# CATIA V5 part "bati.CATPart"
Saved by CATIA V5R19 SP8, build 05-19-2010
Part number: bati
Bounding box of the stored display mesh (mm): x 43.851 to 95, y -33.659 to 317.961, z 22.484 to 100.684
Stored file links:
  G:\EU_thinkMotion\CFAO_2010\MMS_groupe3\MMS_groupe3\A reprendre\amenand\amenand\bati.CATPart
  F:\thinkmotion CFAO v12.1\essuie_glace.CATProduct
  G:\EU_thinkMotion\CFAO_2010\MMS_groupe3\MMS_groupe3\A reprendre\amenand\amenand\squelette_bielle_manivelle.CATPart
  G:\EU_thinkMotion\CFAO_2010\MMS_groupe3\MMS_groupe3\A reprendre\amenand\amenand\bielle_manivelle.CATPart
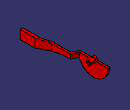
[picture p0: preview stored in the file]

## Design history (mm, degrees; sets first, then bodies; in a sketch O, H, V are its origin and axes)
Set1
  Plane1: linked copy from another document
  Point1: linked copy from another document
  Point2: linked copy from another document
  Plane2 to Plane4: linked copy from another document
Body1 (main body)
  Sketch1 on Plane1, origin (95, 0, 0), H (0, 1, 0), V (0, 0, 1)
    line L1 (317.9612, 88.9602) -> (264.4635, 88.4688)
    point P1 (317.9612, 88.9602)
    point P2 (-34.0239, 85.7271)
    reference projected point E1 (251.964, 88.354) from Point1
    line L2 (-34.0239, 85.7271) -> (-33.6588, 45.9731)
    line L3 (-33.6588, 45.9731) -> (33.3384, 46.5885)
    reference projected point E2 (0.0847, 66.2839) from Point2
    reference projected point E3 (0.0847, 66.2839) from Point2
    line L4 (33.3384, 46.5885) -> (146.176, 67.6258)
    line L5 (146.176, 67.6258) -> (189.1742, 68.0207)
    arc A1 centre (251.964, 88.354) radius 66 from (189.1742, 68.0207) to (317.9612, 88.9602) ccw
    point P7 (251.964, 88.354)
    reference projected point E4 (251.964, 88.354) from Point1
    point P8 (239.4645, 88.2392)
    line L6 (239.4645, 88.2392) -> (-34.0239, 85.7271)
    arc A2 centre (251.964, 88.354) radius 12.5 from (264.4635, 88.4688) to (239.4645, 88.2392) ccw
    point P9 (251.964, 88.354)
    reference projected point E5 (251.964, 88.354) from Point1
    point P11 (239.4645, 88.2392)
    length L3 = 67
    distance L3 E2 = 20
    distance L1 E3 = 20
    radius A1 = 66
    length L5 = 43
    distance P1 P2 = 352
    distance L3 L5 = 20
    radius A2 = 12.5
    coincidence: L1 E1, P7 E4, L1 L6, P9 E5, P8 P11
    fix: L1
    perpendicularity: L1 L2
    parallelism: L3 L1, L5 L1
  Sketch2 on xy-plane, origin (0, 0, 0), H (1, 0, 0), V (0, 1, 0)
    line L1 (83, -33.6588) -> (95, -33.6588)
    point P2 (95, -33.6588)
    reference projected point E1 (95, -33.6588) from vertex [element of Sketch1 | element of Sketch1]
    line L2 (83, -33.6588) -> (83, 46.0526)
    line L3 (95, -33.6588) -> (95, 33.5512)
    line L4 (95, 33.5512) -> (79.896, 92.151)
    point P5 (79.896, 92.151)
    line L5 (79.896, 92.151) -> (79.896, 177.3502)
    line L6 (83, 46.0526) -> (71.396, 91.0732)
    line L7 (71.396, 91.0732) -> (71.396, 171.742)
    line L8 (79.896, 177.3502) -> (52.3512, 189.1371)
    line L9 (52.3512, 189.1371) -> (52.3512, 321.1371)
    line L10 (43.8512, 183.5288) -> (43.8512, 321.1371)
    line L11 (43.8512, 321.1371) -> (52.3512, 321.1371)
    line L12 (71.396, 171.742) -> (43.8512, 183.5288)
    reference intersected line E2 through (83, 0) direction (0, 1) from Plane3
    distance L5 L7 = 8.5
    length L9 = 132
    distance L9 L10 = 8.5
    distance L8 L12 = 8.5
    distance L4 L6 = 8.5
    coincidence: P2 E1, L2 E2
    vertical: L5 V, L7 V, L9 V, L10 V, L3 V
    horizontal: L11 H, L1 H
    fix: P5, L4, L5, L8, L9
  SolidCombine1: FirstComponentProfile Sketch1, FirstComponentDirection Sketch1, SecondComponentProfile Sketch2, SecondComponentDirection Sketch2
  Sketch3 on face of SolidCombine1 from Sketch2.L10, origin (43.8512, 188.6989, 0), H (0, 1, 0), V (0, 0, 1)
    circle A1 centre (63.2651, 88.354) radius 11
    point P1 (63.2651, 88.354)
    reference projected point E1 (63.2651, 88.354) from Point1
    radius A1 = 11
    coincidence: P1 E1
  Pad1: profile Sketch3, direction (1, 0, 0), up to Plane2
  Sketch4 on face of SolidCombine1 from Sketch2.L10, origin (43.8512, 250.7075, 68.7488), H (0, 1, 0), V (0, 0, -1)
    point P1 (1.2565, -19.6052)
    reference projected point E1 (1.2565, -19.6052) from Point1
    coincidence: E1 P1
  Hole1: placed by Sketch4, at (43.8512, 251.964, 88.354) direction (1, 0, 0), diameter 10, through (limit type 6)
  Sketch5 on Plane4, origin (83, -64.134, 0.0122), H (0, 1, 0), V (0, 0, 1)
    circle A1 centre (64.2187, 66.2717) radius 3.5
    point P1 (64.2187, 66.2717)
    reference projected point E1 (64.2187, 66.2717) from Point2
    radius A1 = 3.5
    coincidence: P1 E1
  Pad2: profile Sketch5, direction (-1, 0, 0), length 5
